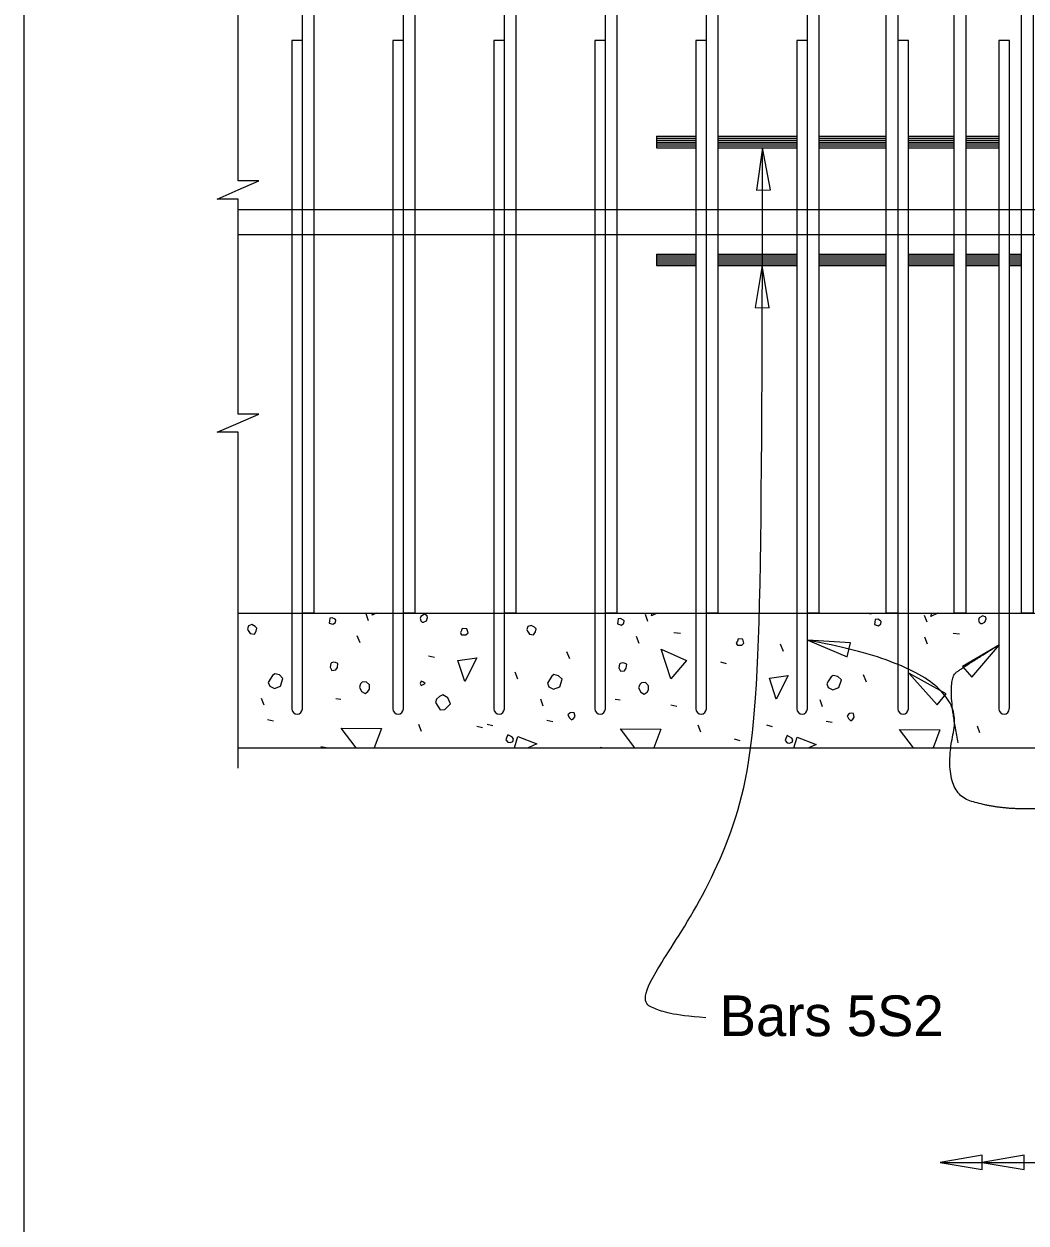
# Model space of a CAD drawing. Extents: x 120587.5 to 120659.6, y 120683.4 to 120715.5.
# Drawn here: x 120587.46 to 120592.42, y 120693.4 to 120699.34 of the extents above; entities that cross this region are included whole.
import ezdxf

# ---------------------------------------------------------------- set-up
doc = ezdxf.new("R2010")
doc.units = 0
for name, color, linetype in [('ActivePts-ConstElements', 7, 'Continuous'), ('AdhocPoint_dp', 7, 'Continuous'), ('Border', 7, 'Continuous'), ('Patterning', 7, 'Continuous'), ('PlotBorder_dp', 7, 'Continuous'), ('TextMisc', 7, 'Continuous')]:
    doc.layers.add(name, color=color, linetype=linetype)

msp = doc.modelspace()

# ---------------------------------------------------------------- linework, layer by layer
at = {"layer": 'ActivePts-ConstElements'}
msp.add_lwpolyline([(120587.4609, 120686.1476), (120628.5115, 120686.1476), (120628.5115, 120712.0937), (120587.4609, 120712.0937)], close=True, dxfattribs=at)
at = {"layer": 'AdhocPoint_dp'}
msp.add_line((120591.9958, 120693.7002), (120603.4029, 120693.7002), dxfattribs=at)
for points in [[(120588.5208, 120699.087), (120588.5208, 120701.3501), (120588.4174, 120701.3501), (120588.5208, 120701.3951), (120588.6241, 120701.4401), (120588.5208, 120701.4401), (120588.5208, 120704.5204)], [(120588.5208, 120698.087), (120588.5208, 120698.4714), (120588.4174, 120698.4714), (120588.5208, 120698.5164), (120588.6241, 120698.5614), (120588.5208, 120698.5614), (120588.5208, 120699.087)], [(120588.5208, 120695.653), (120588.5208, 120697.3162), (120588.4174, 120697.3162), (120588.5208, 120697.3612), (120588.6241, 120697.4062), (120588.5208, 120697.4062), (120588.5208, 120698.087)]]:
    msp.add_lwpolyline(points, dxfattribs=at)
for points in [[(120591.1174, 120698.725), (120591.0863, 120698.5161), (120591.1569, 120698.5175)], [(120591.116, 120698.1417), (120591.0799, 120697.9336), (120591.1504, 120697.9333)], [(120591.3414, 120696.2866), (120591.5361, 120696.2047), (120591.5522, 120696.2734)], [(120592.2893, 120696.2643), (120592.1073, 120696.157), (120592.1528, 120696.1031)], [(120591.8414, 120696.1241), (120591.9817, 120695.9662), (120592.0259, 120696.0212)], [(120591.9958, 120693.7002), (120592.204, 120693.6649), (120592.204, 120693.7355)], [(120592.204, 120693.7002), (120592.4123, 120693.6649), (120592.4123, 120693.7355)]]:
    msp.add_lwpolyline(points, close=True, dxfattribs=at)
for points, degree in [([(120590.8357, 120694.4171), (120590.6661, 120694.4294), (120590.5823, 120694.4626), (120590.4614, 120694.5094), (120591.1134, 120695.3686), (120591.1127, 120696.3911), (120591.1174, 120698.725)], 3), ([(120592.4772, 120695.4523), (120592.2948, 120695.4435), (120592.0006, 120695.5358), (120592.1255, 120696.1436), (120591.3414, 120696.2866)], 2), ([(120592.0858, 120695.7783), (120592.0228, 120696.09), (120592.13, 120696.166), (120592.2893, 120696.2643)], 2)]:
    msp.add_open_spline(points, degree=degree, dxfattribs=at)
at = {"layer": 'Border'}
for p, q in [((120588.8388, 120699.2563), (120588.7867, 120699.2563)), ((120588.7867, 120699.2563), (120588.7867, 120695.9464)), ((120588.8388, 120695.9464), (120588.8388, 120699.2563)), ((120589.3388, 120699.2563), (120589.2867, 120699.2563)), ((120589.2867, 120699.2563), (120589.2867, 120695.9464)), ((120589.3388, 120695.9464), (120589.3388, 120699.2563)), ((120589.8388, 120699.2563), (120589.7867, 120699.2563)), ((120589.7867, 120699.2563), (120589.7867, 120695.9464)), ((120589.8388, 120695.9464), (120589.8388, 120699.2563)), ((120590.3388, 120699.2563), (120590.2867, 120699.2563)), ((120590.2867, 120699.2563), (120590.2867, 120695.9464)), ((120590.3388, 120695.9464), (120590.3388, 120699.2563)), ((120590.8388, 120699.2563), (120590.7867, 120699.2563)), ((120590.7867, 120699.2563), (120590.7867, 120695.9464)), ((120590.8388, 120695.9464), (120590.8388, 120699.2563)), ((120591.3388, 120699.2563), (120591.2867, 120699.2563)), ((120591.2867, 120699.2563), (120591.2867, 120695.9464)), ((120591.3388, 120695.9464), (120591.3388, 120699.2563)), ((120591.8388, 120699.2563), (120591.7867, 120699.2563)), ((120591.7867, 120699.2563), (120591.7867, 120695.9464)), ((120591.8388, 120695.9464), (120591.8388, 120699.2563)), ((120592.3388, 120699.2563), (120592.2867, 120699.2563)), ((120592.2867, 120699.2563), (120592.2867, 120695.9464)), ((120592.3388, 120695.9464), (120592.3388, 120699.2563)), ((120590.5914, 120698.7823), (120590.7867, 120698.7823)), ((120590.5914, 120698.7823), (120590.5914, 120698.725)), ((120590.5914, 120698.7728), (120590.7867, 120698.7728)), ((120590.5914, 120698.7632), (120590.7867, 120698.7632)), ((120590.8961, 120698.7823), (120591.2867, 120698.7823)), ((120590.8961, 120698.7728), (120591.2867, 120698.7728)), ((120590.8961, 120698.7632), (120591.2867, 120698.7632)), ((120591.3961, 120698.7823), (120591.7294, 120698.7823)), ((120591.3961, 120698.7728), (120591.7294, 120698.7728)), ((120591.3961, 120698.7632), (120591.7294, 120698.7632)), ((120591.8388, 120698.7823), (120592.0653, 120698.7823)), ((120591.8388, 120698.7728), (120592.0653, 120698.7728)), ((120591.8388, 120698.7632), (120592.0653, 120698.7632)), ((120592.1226, 120698.7823), (120592.2867, 120698.7823)), ((120592.1226, 120698.7728), (120592.2867, 120698.7728)), ((120592.1226, 120698.7632), (120592.2867, 120698.7632)), ((120590.5914, 120698.7537), (120590.7867, 120698.7537)), ((120590.5914, 120698.7441), (120590.7867, 120698.7441)), ((120590.5914, 120698.7346), (120590.7867, 120698.7346)), ((120590.5914, 120698.725), (120590.7867, 120698.725)), ((120590.8961, 120698.7537), (120591.2867, 120698.7537)), ((120590.8961, 120698.7441), (120591.2867, 120698.7441)), ((120590.8961, 120698.7346), (120591.2867, 120698.7346)), ((120590.8961, 120698.725), (120591.2867, 120698.725)), ((120591.3961, 120698.7537), (120591.7294, 120698.7537)), ((120591.3961, 120698.7441), (120591.7294, 120698.7441)), ((120591.3961, 120698.7346), (120591.7294, 120698.7346)), ((120591.3961, 120698.725), (120591.7294, 120698.725)), ((120591.8388, 120698.7537), (120592.0653, 120698.7537)), ((120591.8388, 120698.7441), (120592.0653, 120698.7441)), ((120591.8388, 120698.7346), (120592.0653, 120698.7346)), ((120591.8388, 120698.725), (120592.0653, 120698.725)), ((120592.1226, 120698.7537), (120592.2867, 120698.7537)), ((120592.1226, 120698.7441), (120592.2867, 120698.7441)), ((120592.1226, 120698.7346), (120592.2867, 120698.7346)), ((120592.1226, 120698.725), (120592.2867, 120698.725)), ((120590.5914, 120698.199), (120590.5914, 120698.1417)), ((120590.5914, 120698.199), (120590.7867, 120698.199)), ((120590.5914, 120698.1894), (120590.7867, 120698.1894)), ((120590.5914, 120698.1799), (120590.7867, 120698.1799)), ((120590.5914, 120698.1703), (120590.7867, 120698.1703)), ((120590.8961, 120698.199), (120591.2867, 120698.199)), ((120590.8961, 120698.1894), (120591.2867, 120698.1894)), ((120590.8961, 120698.1799), (120591.2867, 120698.1799)), ((120590.8961, 120698.1703), (120591.2867, 120698.1703)), ((120591.3961, 120698.199), (120591.7294, 120698.199)), ((120591.3961, 120698.1894), (120591.7294, 120698.1894)), ((120591.3961, 120698.1799), (120591.7294, 120698.1799)), ((120591.3961, 120698.1703), (120591.7294, 120698.1703)), ((120591.8388, 120698.199), (120592.0653, 120698.199)), ((120591.8388, 120698.1894), (120592.0653, 120698.1894)), ((120591.8388, 120698.1799), (120592.0653, 120698.1799)), ((120591.8388, 120698.1703), (120592.0653, 120698.1703)), ((120592.1226, 120698.199), (120592.2867, 120698.199)), ((120592.1226, 120698.1894), (120592.2867, 120698.1894)), ((120592.1226, 120698.1799), (120592.2867, 120698.1799)), ((120592.1226, 120698.1703), (120592.2867, 120698.1703)), ((120592.3388, 120698.199), (120592.3987, 120698.199)), ((120592.3388, 120698.1894), (120592.3987, 120698.1894)), ((120592.3388, 120698.1799), (120592.3987, 120698.1799)), ((120592.3388, 120698.1703), (120592.3987, 120698.1703)), ((120590.5914, 120698.1608), (120590.7867, 120698.1608)), ((120590.5914, 120698.1512), (120590.7867, 120698.1512)), ((120590.5914, 120698.1417), (120590.7867, 120698.1417)), ((120590.8961, 120698.1608), (120591.2867, 120698.1608)), ((120590.8961, 120698.1512), (120591.2867, 120698.1512)), ((120590.8961, 120698.1417), (120591.2867, 120698.1417)), ((120591.3961, 120698.1608), (120591.7294, 120698.1608)), ((120591.3961, 120698.1512), (120591.7294, 120698.1512)), ((120591.3961, 120698.1417), (120591.7294, 120698.1417)), ((120591.8388, 120698.1608), (120592.0653, 120698.1608)), ((120591.8388, 120698.1512), (120592.0653, 120698.1512)), ((120591.8388, 120698.1417), (120592.0653, 120698.1417)), ((120592.1226, 120698.1608), (120592.2867, 120698.1608)), ((120592.1226, 120698.1512), (120592.2867, 120698.1512)), ((120592.1226, 120698.1417), (120592.2867, 120698.1417)), ((120592.3388, 120698.1608), (120592.3987, 120698.1608)), ((120592.3388, 120698.1512), (120592.3987, 120698.1512)), ((120592.3388, 120698.1417), (120592.3987, 120698.1417))]:
    msp.add_line(p, q, dxfattribs=at)
for points in [[(120588.8388, 120704.2537), (120588.8961, 120704.2537), (120588.8961, 120696.4203), (120588.8388, 120696.4203)], [(120589.3388, 120704.2537), (120589.3961, 120704.2537), (120589.3961, 120696.4203), (120589.3388, 120696.4203)], [(120589.8388, 120704.2537), (120589.8961, 120704.2537), (120589.8961, 120696.4203), (120589.8388, 120696.4203)], [(120590.3388, 120704.2537), (120590.3961, 120704.2537), (120590.3961, 120696.4203), (120590.3388, 120696.4203)], [(120590.8388, 120704.2537), (120590.8961, 120704.2537), (120590.8961, 120696.4203), (120590.8388, 120696.4203)], [(120591.3388, 120704.2537), (120591.3961, 120704.2537), (120591.3961, 120696.4204), (120591.3388, 120696.4204)], [(120591.7294, 120704.2537), (120591.7867, 120704.2537), (120591.7867, 120696.4204), (120591.7294, 120696.4204)], [(120592.0653, 120704.2537), (120592.1226, 120704.2537), (120592.1226, 120696.4204), (120592.0653, 120696.4204)], [(120592.3987, 120704.2537), (120592.456, 120704.2537), (120592.456, 120696.4204), (120592.3987, 120696.4204)]]:
    msp.add_lwpolyline(points, close=True, dxfattribs=at)
for centre in [(120588.8128, 120695.9464), (120589.3128, 120695.9464), (120589.8128, 120695.9464), (120590.3128, 120695.9464), (120590.8128, 120695.9464), (120591.3128, 120695.9464), (120591.8128, 120695.9464), (120592.3127, 120695.9464)]:
    msp.add_arc(centre, 0.026, 180, 0, dxfattribs=at)
at = {"layer": 'Patterning'}
for p, q in [((120589.1671, 120696.383), (120589.1547, 120696.4166)), ((120590.2708, 120696.4203), (120590.2719, 120696.4201)), ((120590.5495, 120696.3795), (120590.5371, 120696.4131)), ((120591.6356, 120696.4203), (120591.6543, 120696.4166)), ((120591.9319, 120696.3759), (120591.9195, 120696.4095)), ((120590.6785, 120696.3247), (120590.7103, 120696.3211)), ((120589.1246, 120696.2734), (120589.1105, 120696.3088)), ((120590.507, 120696.2699), (120590.4929, 120696.3052)), ((120591.22, 120696.2313), (120591.2058, 120696.2667)), ((120591.9339, 120696.2663), (120591.9197, 120696.3017)), ((120592.0609, 120696.3211), (120592.0927, 120696.3176)), ((120589.4641, 120696.2098), (120589.4923, 120696.2027)), ((120590.1623, 120696.1938), (120590.1482, 120696.2292)), ((120590.9093, 120696.1789), (120590.9376, 120696.1718)), ((120589.906, 120696.0931), (120589.8919, 120696.1284)), ((120591.6313, 120696.0789), (120591.6172, 120696.1143)), ((120588.6491, 120695.964), (120588.6367, 120695.9976)), ((120589.0044, 120695.9976), (120589.0292, 120695.9941)), ((120590.0315, 120695.9605), (120590.0191, 120695.9941)), ((120590.3868, 120695.9941), (120590.4116, 120695.9906)), ((120591.4139, 120695.957), (120591.4015, 120695.9906)), ((120590.6626, 120695.9658), (120590.6927, 120695.9605)), ((120588.6668, 120695.8933), (120588.6968, 120695.888)), ((120589.4287, 120695.835), (120589.4163, 120695.8686)), ((120589.7027, 120695.8615), (120589.731, 120695.8544)), ((120589.754, 120695.8703), (120589.7823, 120695.8633)), ((120590.0492, 120695.8898), (120590.0792, 120695.8845)), ((120590.8111, 120695.8315), (120590.7987, 120695.865)), ((120591.1364, 120695.8668), (120591.1646, 120695.8597)), ((120591.4316, 120695.8863), (120591.4616, 120695.881)), ((120592.1935, 120695.8279), (120592.1811, 120695.8615)), ((120590.9772, 120695.7973), (120591.0054, 120695.7902)), ((120588.9302, 120695.7607), (120588.9567, 120695.7554)), ((120590.3126, 120695.7572), (120590.3303, 120695.7537))]:
    msp.add_line(p, q, dxfattribs=at)
for points in [[(120588.9709, 120696.3706), (120588.9903, 120696.3653), (120589.0027, 120696.3742), (120589.0044, 120696.3865), (120589.0009, 120696.3901), (120588.9868, 120696.3971), (120588.9744, 120696.3954), (120588.9726, 120696.383), (120588.9709, 120696.3706)], [(120589.1848, 120696.4113), (120589.1875, 120696.4203)], [(120589.2049, 120696.4203), (120589.1848, 120696.4113)], [(120589.4322, 120696.3759), (120589.4393, 120696.3759), (120589.4535, 120696.383), (120589.4588, 120696.3989), (120589.457, 120696.4077), (120589.4428, 120696.4148), (120589.4252, 120696.4042), (120589.4216, 120696.3936), (120589.4252, 120696.383), (120589.4322, 120696.3759)], [(120590.3987, 120696.3671), (120590.4181, 120696.3618), (120590.4305, 120696.3706), (120590.4322, 120696.383), (120590.4287, 120696.3865), (120590.4146, 120696.3936), (120590.4022, 120696.3918), (120590.4004, 120696.3795), (120590.3987, 120696.3671)], [(120590.5671, 120696.4077), (120590.571, 120696.4203)], [(120590.5952, 120696.4203), (120590.5671, 120696.4077)], [(120591.6712, 120696.3636), (120591.6907, 120696.3582), (120591.703, 120696.3671), (120591.7048, 120696.3795), (120591.7013, 120696.383), (120591.6871, 120696.3901), (120591.6747, 120696.3883), (120591.673, 120696.3759), (120591.6712, 120696.3636)], [(120591.9495, 120696.4042), (120591.9545, 120696.4203)], [(120591.9854, 120696.4203), (120591.9495, 120696.4042)], [(120592.197, 120696.3689), (120592.2041, 120696.3689), (120592.2182, 120696.3759), (120592.2235, 120696.3918), (120592.2218, 120696.4007), (120592.2076, 120696.4077), (120592.19, 120696.3971), (120592.1864, 120696.3865), (120592.19, 120696.3759), (120592.197, 120696.3689)], [(120588.5713, 120696.3353), (120588.5802, 120696.3194), (120588.6014, 120696.3158), (120588.6102, 120696.3317), (120588.6138, 120696.3459), (120588.6049, 120696.3547), (120588.589, 120696.3636), (120588.5731, 120696.3582), (120588.5678, 120696.3423), (120588.5713, 120696.3353)], [(120589.6273, 120696.3131), (120589.6485, 120696.3131), (120589.6591, 120696.3237), (120589.6538, 120696.3431), (120589.6308, 120696.3449), (120589.6273, 120696.3343), (120589.622, 120696.3254), (120589.6273, 120696.3131), (120589.6237, 120696.3166)], [(120589.9537, 120696.3317), (120589.9626, 120696.3158), (120589.9838, 120696.3123), (120589.9926, 120696.3282), (120589.9962, 120696.3423), (120589.9873, 120696.3512), (120589.9714, 120696.36), (120589.9555, 120696.3547), (120589.9502, 120696.3388), (120589.9537, 120696.3317)], [(120590.9924, 120696.2613), (120591.0137, 120696.2613), (120591.0243, 120696.2719), (120591.019, 120696.2913), (120590.996, 120696.2931), (120590.9924, 120696.2825), (120590.9871, 120696.2736), (120590.9924, 120696.2613), (120590.9889, 120696.2648)], [(120590.663, 120696.0949), (120590.6153, 120696.2416), (120590.7408, 120696.1868), (120590.663, 120696.0949)], [(120588.9762, 120696.1532), (120588.985, 120696.1373), (120589.0044, 120696.139), (120589.0133, 120696.1514), (120589.015, 120696.1709), (120589.0027, 120696.1762), (120588.9938, 120696.1779), (120588.9832, 120696.1744), (120588.9797, 120696.1709), (120588.9762, 120696.1532)], [(120589.6427, 120696.0819), (120589.6091, 120696.1862), (120589.7028, 120696.1986), (120589.6427, 120696.0819)], [(120590.4055, 120696.1497), (120590.4144, 120696.1337), (120590.4338, 120696.1355), (120590.4427, 120696.1479), (120590.4444, 120696.1673), (120590.432, 120696.1726), (120590.4232, 120696.1744), (120590.4126, 120696.1709), (120590.4091, 120696.1673), (120590.4055, 120696.1497)], [(120588.6774, 120696.0595), (120588.7004, 120696.0471), (120588.7304, 120696.0595), (120588.7428, 120696.0966), (120588.7251, 120696.1143), (120588.7022, 120696.1196), (120588.6915, 120696.1125), (120588.6792, 120696.0931), (120588.6703, 120696.0772), (120588.6774, 120696.0595)], [(120590.0598, 120696.056), (120590.0828, 120696.0436), (120590.1128, 120696.056), (120590.1252, 120696.0931), (120590.1075, 120696.1108), (120590.0845, 120696.1161), (120590.0739, 120696.109), (120590.0616, 120696.0895), (120590.0527, 120696.0736), (120590.0598, 120696.056)], [(120591.1844, 120695.9944), (120591.1508, 120696.0987), (120591.2445, 120696.1111), (120591.1844, 120695.9944)], [(120591.4422, 120696.0524), (120591.4652, 120696.0401), (120591.4952, 120696.0524), (120591.5076, 120696.0895), (120591.4899, 120696.1072), (120591.4669, 120696.1125), (120591.4563, 120696.1055), (120591.444, 120696.086), (120591.4351, 120696.0701), (120591.4422, 120696.0524)], [(120589.1211, 120696.0542), (120589.1317, 120696.033), (120589.1494, 120696.0224), (120589.1635, 120696.033), (120589.1706, 120696.0436), (120589.1706, 120696.0648), (120589.1547, 120696.0807), (120589.1353, 120696.0789), (120589.1264, 120696.0701), (120589.1211, 120696.0542)], [(120589.4269, 120696.063), (120589.4464, 120696.0719), (120589.4393, 120696.0789), (120589.4269, 120696.0842), (120589.4216, 120696.0719), (120589.4269, 120696.063)], [(120590.5035, 120696.0507), (120590.5141, 120696.0294), (120590.5318, 120696.0188), (120590.5459, 120696.0294), (120590.553, 120696.0401), (120590.553, 120696.0613), (120590.5371, 120696.0772), (120590.5176, 120696.0754), (120590.5088, 120696.0666), (120590.5035, 120696.0507)], [(120589.4976, 120695.9782), (120589.5206, 120695.9411), (120589.5436, 120695.9428), (120589.5524, 120695.9517), (120589.5719, 120695.9711), (120589.5595, 120696.0012), (120589.5348, 120696.0153), (120589.5171, 120696.0082), (120589.5029, 120695.9941), (120589.4976, 120695.9782)], [(120590.1606, 120695.9022), (120590.1712, 120695.8916), (120590.1818, 120695.8986), (120590.1888, 120695.9092), (120590.1853, 120695.9269), (120590.1765, 120695.9287), (120590.1641, 120695.9269), (120590.1535, 120695.9163), (120590.1606, 120695.9022)], [(120591.543, 120695.8986), (120591.5536, 120695.888), (120591.5642, 120695.8951), (120591.5712, 120695.9057), (120591.5677, 120695.9234), (120591.5589, 120695.9251), (120591.5465, 120695.9234), (120591.5359, 120695.9128), (120591.543, 120695.8986)], [(120589.1048, 120695.7537), (120589.031, 120695.8509), (120589.2307, 120695.8491), (120589.195, 120695.7537)], [(120589.8565, 120695.782), (120589.8689, 120695.7802), (120589.8813, 120695.7855), (120589.8848, 120695.7961), (120589.8795, 120695.8049), (120589.8689, 120695.812), (120589.8565, 120695.8173), (120589.8494, 120695.8032), (120589.8459, 120695.7926), (120589.8565, 120695.782)], [(120589.8886, 120695.7537), (120589.906, 120695.8102), (120589.9997, 120695.7731), (120589.9564, 120695.7537)], [(120590.4846, 120695.7537), (120590.4133, 120695.8474), (120590.6131, 120695.8456), (120590.5788, 120695.7537)], [(120591.2389, 120695.7784), (120591.2513, 120695.7767), (120591.2636, 120695.782), (120591.2672, 120695.7926), (120591.2619, 120695.8014), (120591.2513, 120695.8085), (120591.2389, 120695.8138), (120591.2318, 120695.7996), (120591.2283, 120695.789), (120591.2389, 120695.7784)], [(120591.2721, 120695.7537), (120591.2884, 120695.8067), (120591.3821, 120695.7696), (120591.3467, 120695.7537)], [(120591.8643, 120695.7537), (120591.7957, 120695.8438), (120591.9955, 120695.8421), (120591.9625, 120695.7537)]]:
    msp.add_lwpolyline(points, dxfattribs=at)
at = {"layer": 'PlotBorder_dp'}
for p, q in [((120588.5208, 120698.4203), (120598.0015, 120698.4203)), ((120588.5208, 120698.2954), (120598.0015, 120698.2954)), ((120588.5208, 120696.4203), (120607.6672, 120696.4203)), ((120588.5208, 120695.7537), (120607.6672, 120695.7537))]:
    msp.add_line(p, q, dxfattribs=at)

# ---------------------------------------------------------------- texts
at = {"layer": 'TextMisc'}
msp.add_text('Bars 5S2', height=0.2016, dxfattribs=at).set_placement((120590.9049, 120694.3257))

doc.saveas('drawing.dxf')
